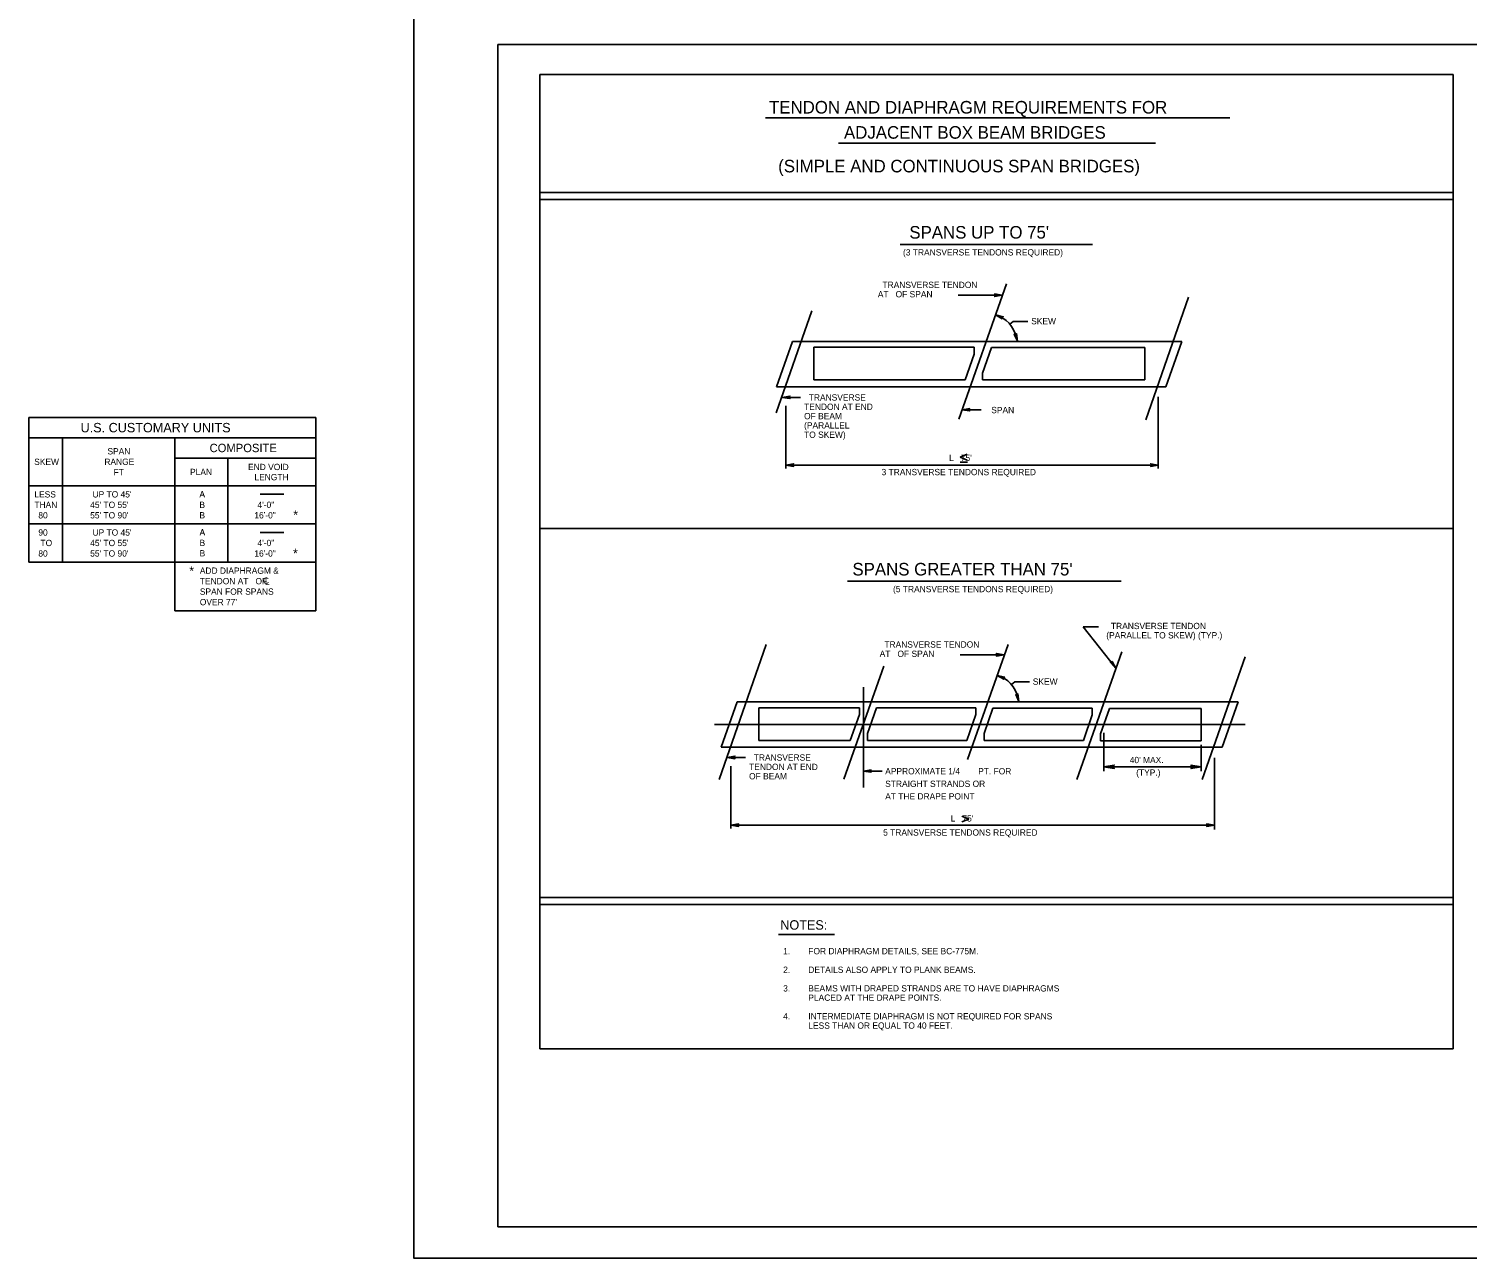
# Model space of a CAD drawing. Extents: x 638791 to 639830, y 298565 to 299753.
# Drawn here: x 638791 to 639477, y 298565 to 299152 of the extents above; entities that cross this region are included whole.
import ezdxf

# ---------------------------------------------------------------- set-up
doc = ezdxf.new("R2010")
doc.units = 0
doc.layers.add('2', color=7, linetype='Continuous')
doc.layers.add('PLT-BNDY', color=7, linetype='Continuous')

msp = doc.modelspace()

# ---------------------------------------------------------------- linework, layer by layer
at = {"layer": '2'}
for p, q in [((639014.29, 298580.48), (639014.29, 299144.48)), ((639014.29, 299144.48), (639800.29, 299144.48)), ((639034.29, 299130.09), (639034.29, 298665.36)), ((639469.95, 299130.09), (639034.29, 299130.09)), ((639469.95, 299130.09), (639469.95, 298665.36)), ((639141.99, 299109.53), (639363.38, 299109.53)), ((639176.81, 299097.4), (639327.91, 299097.4)), ((639469.95, 299073.91), (639034.29, 299073.91)), ((639469.95, 299070.61), (639034.29, 299070.61)), ((639206.22, 299049.09), (639297.81, 299049.09)), ((639233.88, 299024.88), (639254.93, 299024.88)), ((639234.1, 298965.76), (639256.85, 299030.27)), ((639323.25, 298965.47), (639343.67, 299023.94)), ((639147.08, 298968.72), (639164.03, 299017.37)), ((639258.47, 299011.1), (639260.1, 299012.4)), ((639260.1, 299012.4), (639267.09, 299012.4)), ((639147.1, 298981.2), (639154.74, 299002.81)), ((639154.74, 299002.81), (639340.54, 299002.81)), ((639165.01, 298984.45), (639165.01, 299000.05)), ((639165.01, 299000.05), (639241.51, 299000.05)), ((639237.18, 298984.45), (639241.51, 298996.73)), ((639241.51, 298996.73), (639241.51, 299000.05)), ((639245.37, 298987.76), (639249.65, 298999.89)), ((639322.86, 298999.89), (639249.65, 298999.89)), ((639322.86, 298984.45), (639322.86, 298999.89)), ((639332.9, 298981.2), (639340.54, 299002.81)), ((639165.01, 298984.45), (639237.18, 298984.45)), ((639245.37, 298984.45), (639245.37, 298987.76)), ((639322.86, 298984.45), (639245.37, 298984.45)), ((639147.1, 298981.2), (639332.9, 298981.2)), ((639149.92, 298976.16), (639158.54, 298976.16)), ((639329.24, 298942.21), (639329.24, 298976.45)), ((639151.6, 298942.21), (639151.6, 298972.08)), ((639235.72, 298970.15), (639244.82, 298970.15)), ((638790.57, 298897.59), (638790.57, 298966.56)), ((638927.5, 298966.56), (638790.57, 298966.56)), ((638927.5, 298874.39), (638927.5, 298966.56)), ((638927.5, 298956.86), (638790.57, 298956.86)), ((638806.7, 298897.59), (638806.7, 298956.86)), ((638860.3, 298874.39), (638860.3, 298956.86)), ((639234.76, 298947.59), (639238.1, 298949.01)), ((638927.5, 298947.16), (638860.3, 298947.16)), ((638885.5, 298897.59), (638885.5, 298947.16)), ((639151.6, 298943.85), (639329.24, 298943.85)), ((639234.72, 298945.24), (639238.27, 298945.24)), ((639234.76, 298947.59), (639238.1, 298946.17)), ((638927.5, 298933.99), (638790.57, 298933.99)), ((638900.9, 298929.89), (638912.15, 298929.89)), ((638927.5, 298915.79), (638790.57, 298915.79)), ((638900.9, 298911.69), (638912.15, 298911.69)), ((639469.95, 298913.55), (639034.29, 298913.55)), ((638927.5, 298897.59), (638790.57, 298897.59)), ((638857.32, 298897.47), (638857.32, 298897.47)), ((639181.07, 298888.43), (639311.62, 298888.43)), ((638927.5, 298874.39), (638860.3, 298874.39)), ((639300.7, 298866.7), (639293.48, 298866.7)), ((639293.48, 298866.7), (639309.07, 298847.03)), ((639119.76, 298793.81), (639142.22, 298858.29)), ((639234.78, 298853.34), (639255.83, 298853.34)), ((639238.21, 298803.32), (639257.61, 298858.33)), ((639290.44, 298793.81), (639311.91, 298854.7)), ((639350.21, 298793.81), (639370.69, 298852.44)), ((639179.33, 298793.98), (639198.36, 298847.94)), ((639259.23, 298839.15), (639260.86, 298840.45)), ((639260.86, 298840.45), (639267.85, 298840.45)), ((639188.64, 298790.07), (639188.64, 298837.83)), ((639120.82, 298809.25), (639128.45, 298830.86)), ((639128.45, 298830.86), (639367.4, 298830.86)), ((639138.72, 298812.5), (639138.72, 298828.1)), ((639138.72, 298828.1), (639186.68, 298828.1)), ((639186.68, 298824.79), (639186.68, 298828.1)), ((639190.55, 298815.82), (639194.88, 298828.1)), ((639194.88, 298828.1), (639242.27, 298828.1)), ((639242.27, 298824.79), (639242.27, 298828.1)), ((639246.13, 298815.82), (639250.41, 298827.94)), ((639297.79, 298827.94), (639250.41, 298827.94)), ((639297.79, 298824.63), (639297.79, 298827.94)), ((639301.66, 298815.65), (639305.93, 298827.78)), ((639349.66, 298827.78), (639305.93, 298827.78)), ((639349.66, 298812.34), (639349.66, 298827.78)), ((639359.76, 298809.25), (639367.4, 298830.86)), ((639117.6, 298820.06), (639370.61, 298820.06)), ((639182.35, 298812.5), (639186.68, 298824.79)), ((639237.93, 298812.5), (639242.27, 298824.79)), ((639293.52, 298812.5), (639297.79, 298824.63)), ((639138.72, 298812.5), (639182.35, 298812.5)), ((639190.55, 298812.5), (639190.55, 298815.82)), ((639190.55, 298812.5), (639237.93, 298812.5)), ((639246.13, 298812.5), (639246.13, 298815.82)), ((639293.52, 298812.5), (639246.13, 298812.5)), ((639301.66, 298812.34), (639301.66, 298815.65)), ((639349.66, 298812.34), (639301.66, 298812.34)), ((639303.21, 298797.79), (639303.21, 298816.06)), ((639120.82, 298809.25), (639359.76, 298809.25)), ((639123.69, 298804.38), (639132.31, 298804.38)), ((639349.66, 298797.79), (639349.66, 298810.34)), ((639125.37, 298770.43), (639125.37, 298800.29)), ((639188.64, 298797.79), (639197.6, 298797.79)), ((639303.21, 298799.91), (639349.66, 298799.91)), ((639355.99, 298769.94), (639355.99, 298804.18)), ((639125.37, 298772.06), (639355.99, 298772.06)), ((639238.84, 298775.01), (639235.5, 298776.44)), ((639238.84, 298775.01), (639235.5, 298773.59)), ((639469.95, 298737.56), (639034.29, 298737.56)), ((639469.95, 298734.25), (639034.29, 298734.25)), ((639148.12, 298719.97), (639174.87, 298719.97)), ((639469.95, 298665.36), (639034.29, 298665.36)), ((639800.29, 298580.48), (639014.29, 298580.48))]:
    msp.add_line(p, q, dxfattribs=at)
for points in [[(639251.42, 299025.26), (639251.55, 299025.14), (639254.8, 299024.88), (639251.42, 299025.26), (639251.17, 299025.51), (639254.8, 299024.88), (639251.55, 299024.76), (639251.42, 299024.51), (639254.8, 299024.88), (639251.17, 299024.26), (639251.42, 299024.51)], [(639254.65, 299013.86), (639254.65, 299014.11), (639251.65, 299015.49), (639254.65, 299013.86), (639254.78, 299013.61), (639251.65, 299015.49), (639254.78, 299014.36), (639255.03, 299014.61), (639251.65, 299015.49), (639255.28, 299014.61), (639255.03, 299014.61)], [(639261.42, 299006.35), (639261.3, 299006.23), (639262.05, 299002.97), (639261.42, 299006.35), (639261.55, 299006.6), (639262.05, 299002.97), (639260.92, 299006.1), (639260.67, 299006.23), (639262.05, 299002.97), (639260.55, 299006.35), (639260.67, 299006.23)], [(639153.3, 298975.79), (639153.18, 298976.04), (639149.8, 298976.16), (639153.3, 298975.79), (639153.55, 298975.53), (639149.8, 298976.16), (639153.18, 298976.29), (639153.3, 298976.54), (639149.8, 298976.16), (639153.55, 298976.79), (639153.3, 298976.54)], [(639239.23, 298969.77), (639239.1, 298970.02), (639235.72, 298970.15), (639239.23, 298969.77), (639239.35, 298969.65), (639235.72, 298970.15), (639239.1, 298970.4), (639239.23, 298970.65), (639235.72, 298970.15), (639239.35, 298970.77), (639239.23, 298970.65)], [(639155.1, 298943.47), (639154.98, 298943.72), (639151.6, 298943.85), (639155.1, 298943.47), (639155.35, 298943.22), (639151.6, 298943.85), (639154.98, 298943.97), (639155.1, 298944.22), (639151.6, 298943.85), (639155.35, 298944.47), (639155.1, 298944.22)], [(639325.86, 298944.22), (639325.99, 298944.1), (639329.24, 298943.85), (639325.86, 298944.22), (639325.61, 298944.47), (639329.24, 298943.85), (639325.99, 298943.72), (639325.86, 298943.47), (639329.24, 298943.85), (639325.61, 298943.22), (639325.86, 298943.47)], [(639252.32, 298853.71), (639252.45, 298853.59), (639255.7, 298853.34), (639252.32, 298853.71), (639252.07, 298853.97), (639255.7, 298853.34), (639252.45, 298853.21), (639252.32, 298852.96), (639255.7, 298853.34), (639252.07, 298852.71), (639252.32, 298852.96)], [(639307.21, 298849.92), (639307.14, 298849.75), (639309.07, 298847.03), (639307.21, 298849.92), (639307.23, 298850.2), (639309.07, 298847.03), (639306.84, 298849.5), (639306.56, 298849.52), (639309.07, 298847.03), (639306.4, 298849.59), (639306.56, 298849.52)], [(639255.41, 298841.91), (639255.41, 298842.16), (639252.41, 298843.54), (639255.41, 298841.91), (639255.54, 298841.66), (639252.41, 298843.54), (639255.54, 298842.41), (639255.79, 298842.66), (639252.41, 298843.54), (639256.04, 298842.66), (639255.79, 298842.66)], [(639262.18, 298834.41), (639262.06, 298834.28), (639262.81, 298831.03), (639262.18, 298834.41), (639262.31, 298834.66), (639262.81, 298831.03), (639261.68, 298834.16), (639261.43, 298834.28), (639262.81, 298831.03), (639261.31, 298834.41), (639261.43, 298834.28)], [(639127.07, 298804), (639126.95, 298804.25), (639123.57, 298804.38), (639127.07, 298804), (639127.32, 298803.75), (639123.57, 298804.38), (639126.95, 298804.5), (639127.07, 298804.75), (639123.57, 298804.38), (639127.32, 298805), (639127.07, 298804.75)], [(639192.15, 298797.41), (639192.02, 298797.66), (639188.64, 298797.79), (639192.15, 298797.41), (639192.27, 298797.29), (639188.64, 298797.79), (639192.02, 298798.04), (639192.15, 298798.29), (639188.64, 298797.79), (639192.27, 298798.41), (639192.15, 298798.29)], [(639307.98, 298799.32), (639307.8, 298799.67), (639303.21, 298799.92), (639307.98, 298799.32), (639308.23, 298799.12), (639303.21, 298799.92), (639307.8, 298800.15), (639307.97, 298800.49), (639303.21, 298799.92), (639308.23, 298800.72), (639307.97, 298800.49)], [(639345.02, 298799.33), (639345.2, 298799.67), (639349.66, 298799.91), (639345.02, 298799.33), (639344.79, 298799.13), (639349.66, 298799.91), (639345.2, 298800.14), (639345.04, 298800.47), (639349.66, 298799.91), (639344.79, 298800.69), (639345.04, 298800.47)], [(639128.87, 298771.69), (639128.75, 298771.94), (639125.37, 298772.06), (639128.87, 298771.69), (639129.12, 298771.44), (639125.37, 298772.06), (639128.75, 298772.19), (639128.87, 298772.44), (639125.37, 298772.06), (639129.12, 298772.69), (639128.87, 298772.44)], [(639352.61, 298772.44), (639352.74, 298772.32), (639355.99, 298772.06), (639352.61, 298772.44), (639352.36, 298772.69), (639355.99, 298772.06), (639352.74, 298771.94), (639352.61, 298771.69), (639355.99, 298772.06), (639352.36, 298771.44), (639352.61, 298771.69)]]:
    msp.add_lwpolyline(points, dxfattribs=at)
for centre in [(639248, 299002.26), (639248.76, 298830.32)]:
    msp.add_arc(centre, 13.68, 10.16446, 75.07586, dxfattribs=at)
at = {"layer": 'PLT-BNDY'}
msp.add_lwpolyline([(638974.29, 299159.48), (639815.29, 299159.48), (639815.29, 298565.48), (638974.29, 298565.48)], close=True, dxfattribs=at)

# ---------------------------------------------------------------- texts
at = {"layer": '2'}
for s, height, p in [('TENDON AND DIAPHRAGM REQUIREMENTS FOR', 6, (639143.61, 299111.54)), ('ADJACENT BOX BEAM BRIDGES', 6, (639179.35, 299099.54)), ('(SIMPLE AND CONTINUOUS SPAN BRIDGES)', 6, (639147.98, 299083.48)), ("SPANS UP TO 75'", 6, (639210.53, 299051.88)), ('(3 TRANSVERSE TENDONS REQUIRED)', 3.003, (639207.49, 299043.83)), ('  TRANSVERSE TENDON', 3.003, (639195.48, 299028.31)), ('AT   OF SPAN', 3.003, (639195.48, 299023.86)), ('SKEW', 3.003, (639268.63, 299011)), ('  TRANSVERSE', 3.003, (639160.32, 298974.61)), ('TENDON AT END', 3.003, (639160.32, 298970.17)), ('  SPAN', 3.003, (639247.36, 298968.6)), ('OF BEAM', 3.003, (639160.32, 298965.72)), ('(PARALLEL', 3.003, (639160.32, 298961.28)), ('TO SKEW)', 3.003, (639160.32, 298956.83)), ('SPAN', 3, (638828.1, 298948.92)), ('COMPOSITE', 4, (638876.8, 298950.01)), ("L   75'", 3.003, (639229.5, 298945.76)), ('SKEW', 3, (638793.17, 298943.92)), ('RANGE', 3, (638826.63, 298943.92)), ('FT', 3, (638831.02, 298938.92)), ('PLAN', 3, (638867.5, 298939.07)), ('END VOID', 3, (638895.15, 298941.45)), ('3 TRANSVERSE TENDONS REQUIRED', 3.003, (639197.28, 298939.02)), ('LENGTH', 3, (638898.21, 298936.61)), ('LESS', 3, (638793.25, 298928.39)), (" UP TO 45'", 3, (638819.87, 298928.39)), ('A', 3, (638871.92, 298928.39)), ('A', 3, (638871.98, 298928.46)), ('THAN', 3, (638793.24, 298923.39)), ('80', 3, (638795.14, 298918.39)), ("45' TO 55'", 3, (638819.87, 298923.39)), ("55' TO 90'", 3, (638819.87, 298918.39)), ('B', 3, (638871.97, 298923.39)), ('B', 3, (638871.97, 298918.39)), ('16\'-0"', 3, (638898.15, 298918.39)), ('4\'-0"', 3, (638899.64, 298923.39)), ('*', 4.32, (638916.7, 298917.93)), ('90', 3, (638795.14, 298910.19)), ('TO', 3, (638796.17, 298905.19)), ("45' TO 55'", 3, (638819.87, 298905.19)), (" UP TO 45'", 3, (638819.87, 298910.19)), ('A', 3, (638871.98, 298910.26)), ('A', 3, (638872.05, 298910.33)), ('B', 3, (638872.03, 298905.26)), ('4\'-0"', 3, (638899.64, 298905.19)), ('80', 3, (638795.14, 298900.19)), ("55' TO 90'", 3, (638819.87, 298900.19)), ('B', 3, (638872.03, 298900.26)), ('16\'-0"', 3, (638898.15, 298900.19)), ('*', 4.32, (638916.62, 298899.58)), ('*', 4.32, (638867.14, 298891.22)), ('ADD DIAPHRAGM &', 3, (638872.16, 298891.99)), ("SPANS GREATER THAN 75'", 6, (639183.38, 298891.18)), ('TENDON AT   OF', 3, (638872.16, 298886.99)), ('C', 3, (638902.25, 298887.22)), ('L', 3, (638903.16, 298886.63)), ('SPAN FOR SPANS', 3, (638872.16, 298881.99)), ("OVER 77'", 3, (638872.16, 298876.99)), ('(5 TRANSVERSE TENDONS REQUIRED)', 3.003, (639202.74, 298883.2)), ('  TRANSVERSE TENDON', 3.003, (639304.44, 298865.59)), ('  TRANSVERSE TENDON', 3.003, (639196.38, 298856.76)), ('(PARALLEL TO SKEW) (TYP.)', 3.003, (639304.44, 298861.14)), ('AT   OF SPAN', 3.003, (639196.38, 298852.32)), ('SKEW', 3.003, (639269.39, 298839.06)), ('  TRANSVERSE', 3.003, (639134.09, 298802.83)), ("40' MAX.", 3, (639315.63, 298801.66)), ('TENDON AT END', 3.003, (639134.09, 298798.38)), ('APPROXIMATE 1/4', 3, (639199.01, 298796.32)), ('PT. FOR', 3.003, (639243.34, 298796.31)), ('(TYP.)', 3, (639318.7, 298795.66)), ('OF BEAM', 3.003, (639134.09, 298793.94)), ('STRAIGHT STRANDS OR', 3, (639199.01, 298790.32)), ('AT THE DRAPE POINT', 3, (639199.01, 298784.32)), ('5 TRANSVERSE TENDONS REQUIRED', 3.003, (639198.04, 298767.08)), ("L   75'", 3.003, (639230.26, 298773.82)), ('NOTES:', 4.5, (639148.99, 298722.22)), ('1.', 3, (639150.35, 298710.49)), ('FOR DIAPHRAGM DETAILS, SEE BC-775M.', 3, (639162.35, 298710.49)), ('2.', 3, (639150.35, 298701.61)), ('DETAILS ALSO APPLY TO PLANK BEAMS.', 3, (639162.35, 298701.61)), ('3.', 3, (639150.35, 298692.73)), ('BEAMS WITH DRAPED STRANDS ARE TO HAVE DIAPHRAGMS', 3, (639162.35, 298692.73)), ('PLACED AT THE DRAPE POINTS.', 3, (639162.35, 298688.29)), ('4.', 3, (639150.35, 298679.4)), ('INTERMEDIATE DIAPHRAGM IS NOT REQUIRED FOR SPANS', 3, (639162.35, 298679.4)), ('LESS THAN OR EQUAL TO 40 FEET.', 3, (639162.35, 298674.96))]:
    msp.add_text(s, height=height, dxfattribs=at).set_placement(p)
msp.add_text('U.S. CUSTOMARY UNITS', height=4.5, rotation=360, dxfattribs=at).set_placement((638815.28, 298959.46))

doc.saveas('drawing.dxf')
